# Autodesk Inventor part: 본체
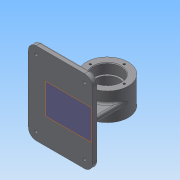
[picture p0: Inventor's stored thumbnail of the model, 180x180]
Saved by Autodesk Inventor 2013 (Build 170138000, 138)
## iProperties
Created: 2019-09
Part Number: 본체
Material: 일반
Document SubType Name: Modeling
Designer: Administrator
Density: 1 g/cm^3
Author: Administrator
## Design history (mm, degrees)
sketch "스케치1"
  geometry: C1 r 32 at (0, 0); 1 further point
  constraints: 1 centre point, 1 coincident
  dimensions: "d0" = 64 diameter of C1
extrude "돌출1" new body sketch "스케치1" stored distance "d1" = 42; taper "d2" = 0 deg
hole "구멍1" diameter "d5" = 36; stored, may be unused: countersink angle "d9" = 90 deg, drill point angle "d11" = 118 deg; dims "d3" = 10, "d4" = 10, "d6" = 6, "d7" = 42, "d8" = 15, "d10" = 8
sketch "스케치2"
  geometry: C1 r 18 at (0, 0) reference; C2 r 32 at (0, 0) reference; C3 r 21 at (0, 0)
  constraints: 1 centre point, 1 coincident
  dimensions: "d12" = 42 diameter of C3
extrude "돌출2" cut sketch "스케치2" distance "d13" = 15; taper "d14" = 0 deg
fillet "모깎기1" dims "d15" = 0.3
chamfer "모따기1" distance "d16" = 1; stored, may be unused: second distance "d17" = 2, angle "d18" = 45 deg
sketch "스케치3"
  geometry: C1 r 32 at (0, 0) reference; 1 further point
  constraints: 1 vertical alignment
  dimensions: "d19" = 26 distance of C1.centre point (0, 26)
hole "구멍2" sketch "스케치3" at (0, 26) diameter "d20" = 3.242; stored, may be unused: countersink angle "d24" = 90 deg, drill point angle "d26" = 118 deg; dims "d21" = 8, "d22" = 42, "d23" = 15, "d25" = 10
node "작업 평면1"
sketch "스케치4"
  geometry: L1 (62, 63)-(-36, 63); L2 (-36, 63)-(-36, -63); L3 (-36, -63)-(62, -63); L4 (62, -63)-(62, 63); 2 further points
  constraints: 8 end point, 2 parallel, 1 horizontal, 1 horizontal alignment, 1 midpoint, 1 perpendicular
  dimensions: "d31" = 126 distance of L1.end L2.end; "d33" = 62 distance from line of L4 point (0, 0); "d34" = 98 distance of L2.end L3.end
extrude "돌출3" join sketch "스케치4" distance "d35" = 9; taper "d36" = 0 deg
sketch "스케치5"
  geometry: L1 (-32, -4)-(32, -4); L2 (32, -4)-(32, 4); L3 (32, 4)-(-32, 4); L4 (-32, 4)-(-32, -4); L5 (-4, -17)-(4, -17); L6 (4, -17)-(4, 17); L7 (4, 17)-(-4, 17); L8 (-4, 17)-(-4, -17); 3 further points
  constraints: 16 end point, 4 parallel, 2 horizontal, 2 midpoint, 2 perpendicular, 1 horizontal alignment, 1 vertical alignment
  dimensions: "d37" = 8 distance of L2.end L1.end; "d38" = 8 distance of L7.end L6.end; "d39" = 34 distance of L5.end L6.end; "d40" = 17 distance from line of point (0, 0) L5; "d41" = 64 distance of L2.end L3.end; "d56" = 32 distance from line of point (0, 0) L4
extrude "돌출4" join sketch "스케치5" stored distance "d43" = 9; taper "d44" = 0 deg
fillet "모깎기2" dims "d45" = 12
sketch "스케치6"
  geometry: A1 r 12 centre (-50, 51) between (-50, 63) and (-62, 51) reference; A2 r 12 centre (-50, -51) between (-62, -51) and (-50, -63) reference; A3 r 12 centre (24, -51) between (24, -63) and (36, -51) reference; A4 r 12 centre (24, 51) between (36, 51) and (24, 63) reference; 5 further points
  constraints: 4 coincident
hole "구멍3" sketch "스케치6" at (-50, 51), (24, 51), (24, -51), (-50, -51) diameter "d46" = 4.5; stored, may be unused: countersink angle "d50" = 90 deg, drill point angle "d52" = 118 deg; dims "d47" = 8, "d48" = 8, "d49" = 4.4, "d51" = 10
fillet "모깎기3" dims "d53" = 3
fillet "모깎기6" dims "d57" = 3
fillet "모깎기7" dims "d58" = 3
fillet "모깎기8" dims "d59" = 3
sketch "스케치7"
  geometry: L1 (-62, 51)-(-62, -51) reference; 2 further points
  constraints: 1 horizontal alignment, 1 other
  dimensions: "d60" = 10 distance from line of L1 point (-52, 0)
feature "엠보싱1" sketch "스케치7" dims "d61" = 0.5, "d62" = 0
node "솔리드1"
pattern_circular "원형 패턴1" dims angle "d28" = 360 deg
mirror "대칭1"
other parameters: "d30" = -59
